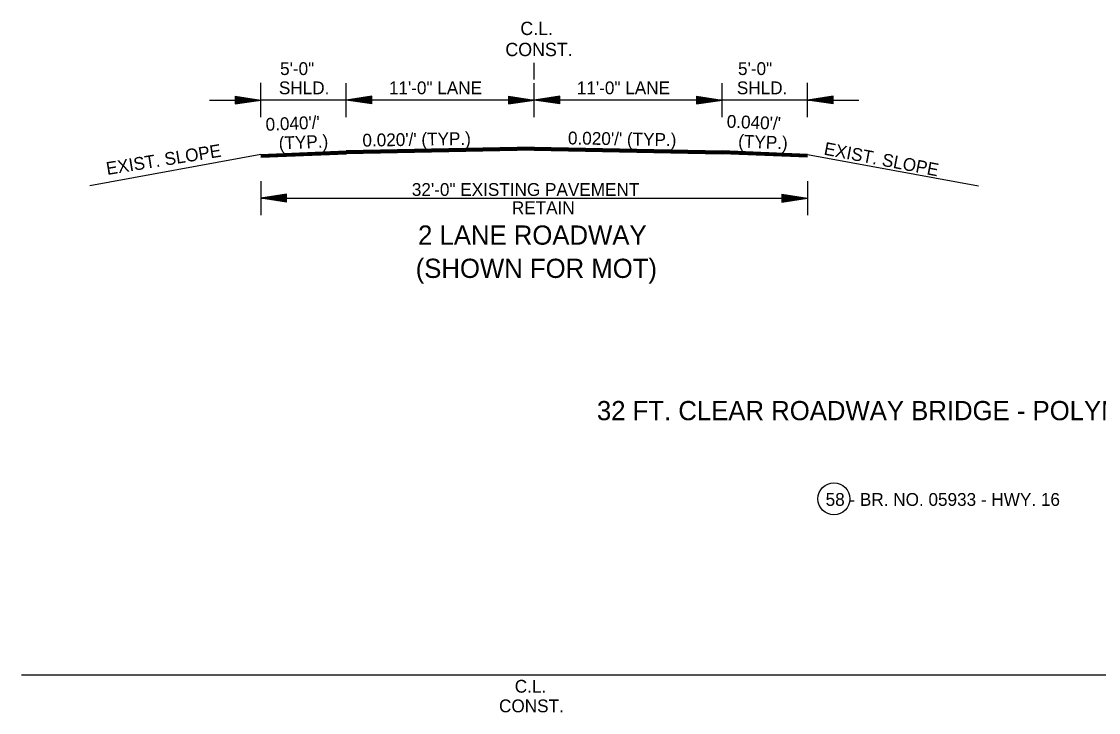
# Model space of a CAD drawing. Extents: x 550980 to 1930787, y -1972975 to 596640.
# Drawn here: x 551010 to 551641, y -1972456 to -1972052 of the extents above; entities that cross this region are included whole.
import ezdxf

# ---------------------------------------------------------------- set-up
doc = ezdxf.new("R2010")
doc.units = 0
doc.layers.add('R_Border', color=7, linetype='Continuous')
doc.layers.add('R_Draft', color=7, linetype='Continuous')

msp = doc.modelspace()

# ---------------------------------------------------------------- linework, layer by layer
at = {"layer": 'R_Border'}
msp.add_line((551010.32, -1972434.47), (552071.59, -1972434.47), dxfattribs=at)
msp.add_circle((551485.76, -1972331.34), 9.34, dxfattribs=at)
at = {"layer": 'R_Draft'}
for p, q in [((551310.35, -1972085.74), (551310.35, -1972075.87)), ((551150.35, -1972107.76), (551150.35, -1972087.76)), ((551200.35, -1972107.76), (551200.35, -1972087.86)), ((551310.35, -1972107.76), (551310.35, -1972087.86)), ((551420.35, -1972107.76), (551420.35, -1972087.86)), ((551470.35, -1972107.76), (551470.35, -1972087.76)), ((551120.35, -1972097.76), (551150.35, -1972097.76)), ((551135.35, -1972095.51), (551150.35, -1972097.76)), ((551135.35, -1972095.51), (551135.35, -1972100.01)), ((551135.35, -1972095.88), (551147.84, -1972097.76)), ((551135.35, -1972096.26), (551145.26, -1972097.76)), ((551135.35, -1972096.64), (551142.76, -1972097.76)), ((551135.35, -1972097.03), (551140.22, -1972097.76)), ((551135.35, -1972097.4), (551137.72, -1972097.76)), ((551135.35, -1972100.01), (551150.35, -1972097.76)), ((551135.35, -1972098.49), (551140.22, -1972097.76)), ((551135.35, -1972099.25), (551145.26, -1972097.76)), ((551135.35, -1972099.63), (551147.84, -1972097.76)), ((551135.35, -1972098.87), (551142.76, -1972097.76)), ((551135.35, -1972098.11), (551137.72, -1972097.76)), ((551200.35, -1972097.76), (551150.35, -1972097.76)), ((551215.35, -1972095.51), (551200.35, -1972097.76)), ((551310.35, -1972097.76), (551200.35, -1972097.76)), ((551215.35, -1972100.01), (551200.35, -1972097.76)), ((551215.35, -1972095.88), (551202.85, -1972097.76)), ((551215.35, -1972099.63), (551202.85, -1972097.76)), ((551215.35, -1972096.26), (551205.43, -1972097.76)), ((551215.35, -1972099.25), (551205.43, -1972097.76)), ((551215.35, -1972096.64), (551207.93, -1972097.76)), ((551215.35, -1972098.87), (551207.93, -1972097.76)), ((551215.35, -1972097.02), (551210.47, -1972097.76)), ((551215.35, -1972098.48), (551210.47, -1972097.76)), ((551215.35, -1972097.4), (551212.98, -1972097.76)), ((551215.35, -1972098.11), (551212.98, -1972097.76)), ((551215.35, -1972100.01), (551215.35, -1972095.51)), ((551295.35, -1972095.51), (551310.35, -1972097.76)), ((551295.35, -1972095.51), (551295.35, -1972100.01)), ((551295.35, -1972095.88), (551307.84, -1972097.76)), ((551295.35, -1972096.26), (551305.26, -1972097.76)), ((551295.35, -1972096.64), (551302.76, -1972097.76)), ((551295.35, -1972097.03), (551300.22, -1972097.76)), ((551295.35, -1972097.4), (551297.72, -1972097.76)), ((551295.35, -1972100.01), (551310.35, -1972097.76)), ((551295.35, -1972098.49), (551300.22, -1972097.76)), ((551295.35, -1972099.25), (551305.26, -1972097.76)), ((551295.35, -1972099.63), (551307.84, -1972097.76)), ((551295.35, -1972098.87), (551302.76, -1972097.76)), ((551295.35, -1972098.11), (551297.72, -1972097.76)), ((551325.35, -1972095.51), (551310.35, -1972097.76)), ((551420.35, -1972097.76), (551310.35, -1972097.76)), ((551325.35, -1972100.01), (551310.35, -1972097.76)), ((551325.35, -1972095.88), (551312.85, -1972097.76)), ((551325.35, -1972099.63), (551312.85, -1972097.76)), ((551325.35, -1972096.26), (551315.43, -1972097.76)), ((551325.35, -1972099.25), (551315.43, -1972097.76)), ((551325.35, -1972096.64), (551317.93, -1972097.76)), ((551325.35, -1972098.87), (551317.93, -1972097.76)), ((551325.35, -1972097.02), (551320.47, -1972097.76)), ((551325.35, -1972098.48), (551320.47, -1972097.76)), ((551325.35, -1972097.4), (551322.98, -1972097.76)), ((551325.35, -1972098.11), (551322.98, -1972097.76)), ((551325.35, -1972100.01), (551325.35, -1972095.51)), ((551405.35, -1972095.51), (551420.35, -1972097.76)), ((551405.35, -1972095.51), (551405.35, -1972100.01)), ((551405.35, -1972095.88), (551417.84, -1972097.76)), ((551405.35, -1972096.26), (551415.26, -1972097.76)), ((551405.35, -1972096.64), (551412.76, -1972097.76)), ((551405.35, -1972097.03), (551410.22, -1972097.76)), ((551405.35, -1972097.4), (551407.72, -1972097.76)), ((551405.35, -1972100.01), (551420.35, -1972097.76)), ((551405.35, -1972098.49), (551410.22, -1972097.76)), ((551405.35, -1972099.25), (551415.26, -1972097.76)), ((551405.35, -1972099.63), (551417.84, -1972097.76)), ((551405.35, -1972098.87), (551412.76, -1972097.76)), ((551405.35, -1972098.11), (551407.72, -1972097.76)), ((551470.35, -1972097.76), (551420.35, -1972097.76)), ((551485.35, -1972095.51), (551470.35, -1972097.76)), ((551485.35, -1972100.01), (551470.35, -1972097.76)), ((551470.35, -1972097.76), (551500.35, -1972097.76)), ((551485.35, -1972095.88), (551472.85, -1972097.76)), ((551485.35, -1972099.63), (551472.85, -1972097.76)), ((551485.35, -1972096.26), (551475.43, -1972097.76)), ((551485.35, -1972099.25), (551475.43, -1972097.76)), ((551485.35, -1972096.64), (551477.93, -1972097.76)), ((551485.35, -1972098.87), (551477.93, -1972097.76)), ((551485.35, -1972097.02), (551480.47, -1972097.76)), ((551485.35, -1972098.48), (551480.47, -1972097.76)), ((551485.35, -1972097.4), (551482.98, -1972097.76)), ((551485.35, -1972098.11), (551482.98, -1972097.76)), ((551485.35, -1972100.01), (551485.35, -1972095.51)), ((551150.35, -1972129.56), (551050.28, -1972147.94)), ((551150.35, -1972129.56), (551200.35, -1972127.56)), ((551150.35, -1972129.86), (551200.36, -1972127.86)), ((551150.35, -1972130.16), (551200.37, -1972128.16)), ((551150.35, -1972130.46), (551200.38, -1972128.46)), ((551150.35, -1972130.76), (551200.39, -1972128.76)), ((551150.35, -1972131.06), (551200.41, -1972129.06)), ((551150.35, -1972131.26), (551200.41, -1972129.26)), ((551310.35, -1972125.36), (551200.35, -1972127.56)), ((551310.35, -1972125.66), (551200.35, -1972127.86)), ((551310.36, -1972125.96), (551200.35, -1972128.16)), ((551310.36, -1972126.26), (551200.35, -1972128.46)), ((551310.37, -1972126.56), (551200.35, -1972128.76)), ((551310.38, -1972126.86), (551200.35, -1972129.06)), ((551310.38, -1972127.06), (551200.35, -1972129.26)), ((551310.31, -1972127.06), (551420.35, -1972129.26)), ((551310.32, -1972126.56), (551420.35, -1972128.76)), ((551310.32, -1972126.86), (551420.35, -1972129.06)), ((551310.33, -1972125.96), (551420.35, -1972128.16)), ((551310.33, -1972126.26), (551420.35, -1972128.46)), ((551310.34, -1972125.66), (551420.35, -1972127.86)), ((551310.35, -1972125.36), (551420.35, -1972127.56)), ((551470.35, -1972131.26), (551420.28, -1972129.26)), ((551470.35, -1972131.06), (551420.29, -1972129.06)), ((551470.35, -1972130.76), (551420.3, -1972128.76)), ((551470.35, -1972130.46), (551420.31, -1972128.46)), ((551470.35, -1972130.16), (551420.32, -1972128.16)), ((551470.35, -1972129.86), (551420.33, -1972127.86)), ((551470.35, -1972129.56), (551420.35, -1972127.56)), ((551470.35, -1972129.56), (551570.41, -1972147.94)), ((551150.35, -1972145.22), (551150.35, -1972165.22)), ((551470.35, -1972145.22), (551470.35, -1972165.22)), ((551165.35, -1972152.97), (551150.35, -1972155.22)), ((551165.35, -1972153.35), (551152.85, -1972155.22)), ((551165.35, -1972153.73), (551155.43, -1972155.22)), ((551165.35, -1972154.1), (551157.93, -1972155.22)), ((551165.35, -1972154.49), (551160.47, -1972155.22)), ((551165.35, -1972154.87), (551162.98, -1972155.22)), ((551165.35, -1972157.47), (551165.35, -1972152.97)), ((551455.35, -1972152.97), (551470.35, -1972155.22)), ((551455.35, -1972152.97), (551455.35, -1972157.47)), ((551455.35, -1972153.35), (551467.84, -1972155.22)), ((551455.35, -1972153.73), (551465.26, -1972155.22)), ((551455.35, -1972154.1), (551462.76, -1972155.22)), ((551455.35, -1972154.49), (551460.22, -1972155.22)), ((551455.35, -1972154.87), (551457.72, -1972155.22)), ((551150.35, -1972155.22), (551470.35, -1972155.22)), ((551165.35, -1972157.47), (551150.35, -1972155.22)), ((551165.35, -1972157.1), (551152.85, -1972155.22)), ((551165.35, -1972156.71), (551155.43, -1972155.22)), ((551165.35, -1972156.34), (551157.93, -1972155.22)), ((551165.35, -1972155.95), (551160.47, -1972155.22)), ((551165.35, -1972155.57), (551162.98, -1972155.22)), ((551455.35, -1972157.47), (551470.35, -1972155.22)), ((551455.35, -1972155.96), (551460.22, -1972155.22)), ((551455.35, -1972156.71), (551465.26, -1972155.22)), ((551455.35, -1972157.1), (551467.84, -1972155.22)), ((551455.35, -1972156.34), (551462.76, -1972155.22)), ((551455.35, -1972155.57), (551457.72, -1972155.22))]:
    msp.add_line(p, q, dxfattribs=at)

# ---------------------------------------------------------------- texts
at = {"layer": 'R_Border'}
for s, height, p in [('(SHOWN FOR MOT)', 11.25, (551240.98, -1972201.94)), ('C.L.', 7.5, (551298.97, -1972444.87)), ('CONST.', 7.5, (551289.76, -1972456.37))]:
    msp.add_text(s, height=height, dxfattribs=at).set_placement(p)
at = {"layer": 'R_Draft'}
for s, height, p in [('C.L.', 7.8, (551302.24, -1972059.67)), ('CONST.', 7.8, (551293.46, -1972072.03)), ('5\'-0"', 7.5, (551161.62, -1972083.1)), ('5\'-0" ', 7.5, (551429.63, -1972083.1)), ('SHLD.', 7.5, (551160.94, -1972094.35)), ('11\'-0" LANE', 7.5, (551225.29, -1972094.35)), ('11\'-0" LANE', 7.5, (551335.29, -1972094.35)), ('SHLD.', 7.5, (551428.95, -1972094.35)), ('32\'-0" EXISTING PAVEMENT', 7.5, (551238.74, -1972153.9)), ('RETAIN', 7.5, (551297.26, -1972164.62)), ('2 LANE ROADWAY', 11.25, (551242.38, -1972182.46)), ('32 FT. CLEAR ROADWAY BRIDGE - POLYMER OVERLAY', 11.25, (551347.04, -1972285.27)), ('58 - BR. NO. 05933 - HWY. 16', 7.5, (551480.9, -1972335.45))]:
    msp.add_text(s, height=height, dxfattribs=at).set_placement(p)
for s, rotation, p in [("0.040'/' ", 2.44797, (551153.31, -1972115.81)), ("0.040'/' ", 357.55203, (551422.89, -1972113.9)), ("0.020'/' (TYP.)", 0.97192, (551209.87, -1972125.06)), ("0.020'/' (TYP.)", 359.02808, (551330.05, -1972123.69)), ('(TYP.)', 2.44797, (551160.99, -1972126.74)), ('(TYP.)', 357.55203, (551429.61, -1972125.45)), ('EXIST. SLOPE', 349.11714, (551479.47, -1972129.65)), ('EXIST. SLOPE', 9.15344, (551060.48, -1972141.67))]:
    msp.add_text(s, height=7.5, rotation=rotation, dxfattribs=at).set_placement(p)

doc.saveas('drawing.dxf')
